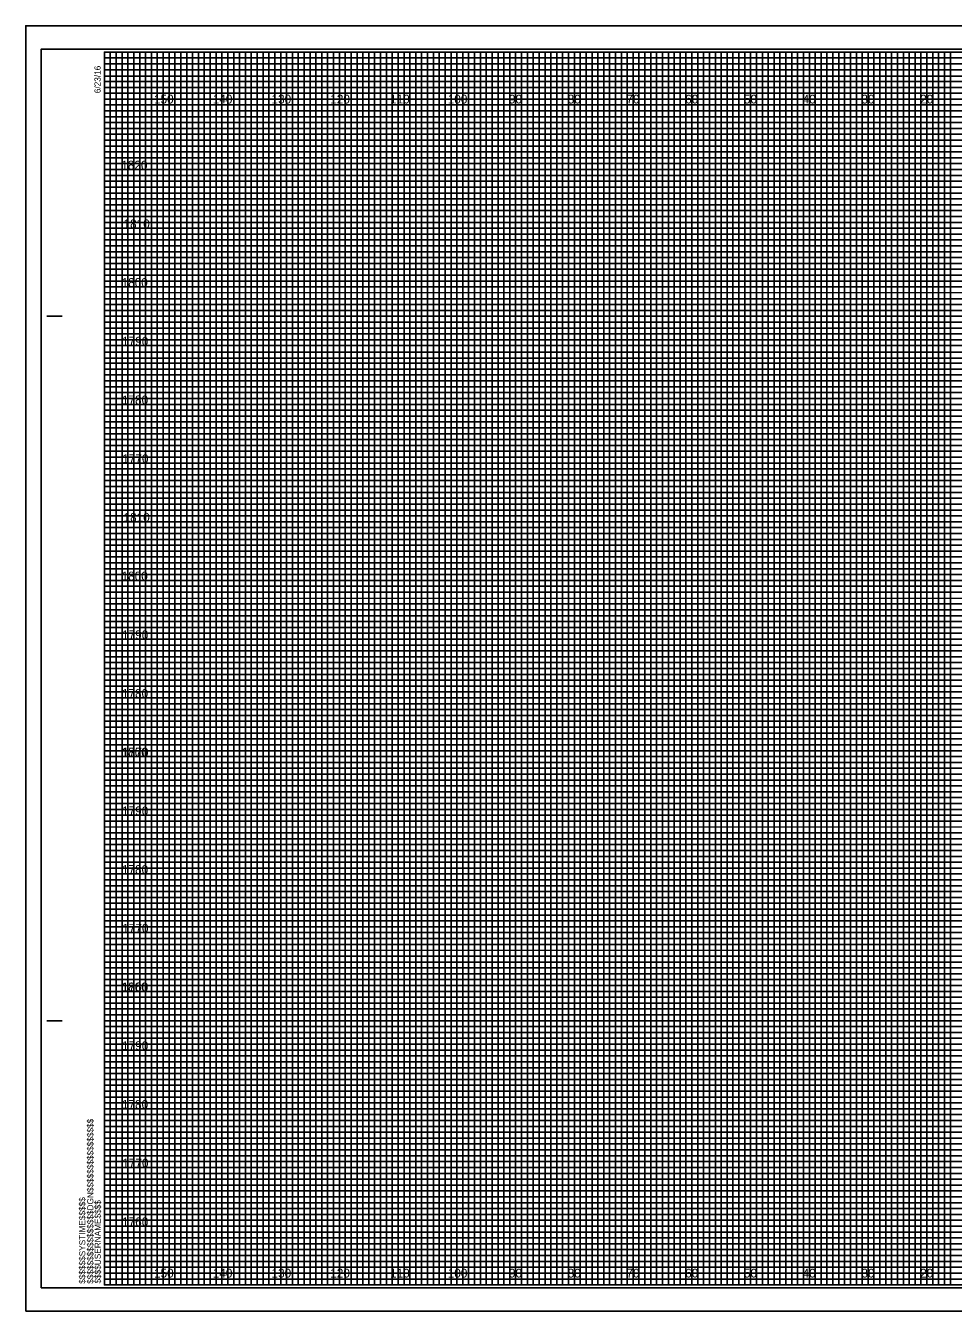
# Model space of a CAD drawing. Extents: x -13 to 323, y -5 to 874.
# Drawn here: x -13.4 to 144.5, y 215.5 to 434.5 of the extents above; entities that cross this region are included whole.
import ezdxf

# ---------------------------------------------------------------- set-up
doc = ezdxf.new("R2010")
doc.units = 0
for name, color, linetype in [('Prop XS Earthwork Shape', 7, 'Continuous'), ('Raster_Level_0', 7, 'Continuous'), ('Scratch_Level_3', 7, 'Continuous'), ('Sheet Cross Section CELL', 7, 'Continuous'), ('Sheet Cross Section Grid Middle CELL', 7, 'Continuous'), ('Sheet Cross Section Grid Minor 1 CELL', 7, 'Continuous'), ('Sheet Cross Section Grid Minor 2 CELL', 7, 'Continuous'), ('Sheet Cutting Line CELL', 7, 'Continuous'), ('Sheet DOT Grid CELL', 7, 'Continuous'), ('Sheet Plot Border Inside CELL', 7, 'Continuous'), ('Sheet Plot Border Outside CELL', 7, 'Continuous')]:
    doc.layers.add(name, color=color, linetype=linetype)

msp = doc.modelspace()

# ---------------------------------------------------------------- linework, layer by layer
at = {"layer": 'Prop XS Earthwork Shape'}
for p, q in [((10, 430), (0, 430)), ((10, 220), (10, 430)), ((30, 430), (20, 430)), ((20, 430), (20, 220)), ((30, 220), (30, 430)), ((50, 430), (40, 430)), ((40, 430), (40, 220)), ((50, 220), (50, 430)), ((70, 430), (60, 430)), ((60, 430), (60, 220)), ((70, 220), (70, 430)), ((90, 430), (80, 430)), ((80, 430), (80, 220)), ((90, 220), (90, 430)), ((110, 430), (100, 430)), ((100, 430), (100, 220)), ((110, 220), (110, 430)), ((130, 430), (120, 430)), ((120, 430), (120, 220)), ((130, 220), (130, 430)), ((150, 430), (140, 430)), ((140, 430), (140, 220)), ((20, 220), (10, 220)), ((40, 220), (30, 220)), ((60, 220), (50, 220)), ((80, 220), (70, 220)), ((100, 220), (90, 220)), ((120, 220), (110, 220)), ((140, 220), (130, 220))]:
    msp.add_line(p, q, dxfattribs=at)
for points in [[(0, 420), (320, 420), (320, 410), (0, 410)], [(0, 400), (320, 400), (320, 390), (0, 390)], [(0, 380), (320, 380), (320, 370), (0, 370)], [(0, 360), (320, 360), (320, 350), (0, 350)], [(0, 340), (320, 340), (320, 330), (0, 330)], [(0, 320), (320, 320), (320, 310), (0, 310)], [(0, 300), (320, 300), (320, 290), (0, 290)], [(0, 280), (320, 280), (320, 270), (0, 270)], [(0, 260), (320, 260), (320, 250), (0, 250)], [(0, 240), (320, 240), (320, 230), (0, 230)]]:
    msp.add_lwpolyline(points, dxfattribs=at)
at = {"layer": 'Sheet Cross Section CELL'}
for p, q in [((-9.8, 385), (-7.3, 385)), ((-9.7, 385), (-7.2, 385)), ((-9.8, 265), (-7.3, 265)), ((-9.7, 265), (-7.2, 265)), ((0, 220), (0, 220)), ((0, 220), (0, 220)), ((0, 220), (0, 220)), ((0, 220), (0, 220)), ((0, 220), (0, 220)), ((0, 220), (0, 220)), ((0, 220), (0, 220))]:
    msp.add_line(p, q, dxfattribs=at)
msp.add_lwpolyline([(320, 430), (0, 430), (0, 220), (320, 220)], close=True, dxfattribs=at)
at = {"layer": 'Sheet Cross Section Grid Middle CELL'}
for points in [[(0, 430), (5, 430), (5, 220), (15, 220), (15, 430), (25, 430), (25, 220), (35, 220), (35, 430), (45, 430), (45, 220), (55, 220), (55, 430), (65, 430), (65, 220), (75, 220), (75, 430), (85, 430), (85, 220), (95, 220), (95, 430), (105, 430), (105, 220), (115, 220), (115, 430), (125, 430), (125, 220), (135, 220), (135, 430), (145, 430)], [(0, 425), (275, 425)], [(0, 405), (320, 405), (320, 415), (0, 415)], [(0, 385), (320, 385), (320, 395), (0, 395)], [(0, 365), (320, 365), (320, 375), (0, 375)], [(0, 345), (320, 345), (320, 355), (0, 355)], [(0, 325), (320, 325), (320, 335), (0, 335)], [(0, 305), (320, 305), (320, 315), (0, 315)], [(0, 285), (320, 285), (320, 295), (0, 295)], [(0, 265), (320, 265), (320, 275), (0, 275)], [(0, 245), (320, 245), (320, 255), (0, 255)], [(0, 225), (320, 225), (320, 235), (0, 235)]]:
    msp.add_lwpolyline(points, dxfattribs=at)
at = {"layer": 'Sheet Cross Section Grid Minor 1 CELL'}
for p, q in [((0, 429), (260, 429)), ((260, 427.98), (0, 427.98)), ((0, 427.98), (0, 427)), ((0, 427), (260, 427)), ((260, 425.89), (0, 425.89)), ((0, 425.89), (0, 424)), ((0, 424), (320, 424))]:
    msp.add_line(p, q, dxfattribs=at)
for points in [[(0, 423), (270, 423), (320, 423), (320, 422), (0, 422)], [(0, 421), (320, 421), (320, 419), (0, 419)], [(0, 418), (320, 418), (320, 417), (0, 416.98)], [(0, 416), (320, 416), (320, 414), (0, 414)], [(0, 413), (320, 413), (320, 412), (0, 412)], [(0, 411), (320, 411), (320, 409), (0, 409)], [(0, 408), (320, 408), (320, 407), (0, 407)], [(0, 406), (320, 406), (320, 404), (0, 404)], [(0, 403), (320, 403), (320, 402), (0, 402)], [(0, 401), (320, 401), (320, 399), (0, 399)], [(0, 398), (320, 398), (320, 397), (0, 397)], [(0, 396), (320, 396), (320, 393.95), (320, 393), (320, 392), (0, 392)], [(0, 394), (320, 394), (320, 393), (0, 393)], [(0, 391), (320, 391), (320, 389), (0, 389.03)], [(0, 389.03), (320, 389), (320, 388), (0, 388)], [(0, 387), (320, 387), (320, 386), (0, 386)], [(0, 384), (320, 384), (320, 383), (0, 383)], [(0, 382), (320, 382), (320, 381), (0, 381)], [(-0.07, 378.89), (320, 378.89), (320, 377.88), (-0.07, 377.88)], [(0, 377), (320, 377), (320, 376), (0, 376)], [(0, 374), (320, 374), (320, 373), (0, 373)], [(0, 372), (320, 372), (320, 371), (0, 371)], [(0, 369), (320, 369), (320, 368), (0, 368)], [(0, 367), (320, 367), (320, 366), (0, 366)], [(0, 364), (320, 364), (320, 363), (0, 363)], [(0, 362), (320, 362), (320, 361), (0, 361)], [(0, 359), (320, 359), (319.99, 357.98), (0, 358)], [(0, 357), (320, 357), (320, 356), (0, 356)], [(0, 354), (320, 354), (320, 353), (0, 353)], [(0, 352), (320, 352), (320, 351), (0, 351)], [(0, 349), (320, 349), (320, 348), (0, 348)], [(0, 347), (320, 347), (320, 346), (0, 346)], [(0, 344), (320, 344), (320, 343), (0, 343)], [(0, 342), (320, 342), (320, 341), (0, 341)], [(0, 339), (320, 339), (320, 338), (0, 338)], [(0, 336.99), (320.07, 336.91), (320, 336), (0, 336)], [(0, 334), (320, 334), (320, 333), (0, 333)], [(0, 332), (320, 332), (320, 331), (0, 331)], [(0, 329), (320, 329), (320, 328), (0, 328)], [(0, 327), (320, 327), (320, 326), (0, 326)], [(0, 324), (320, 324), (320, 323), (0, 323)], [(0, 322), (320, 322), (320, 321), (0, 321)], [(0, 319), (320, 319), (320, 318), (0, 318)], [(0, 317), (320, 317), (320, 316), (0, 316)], [(0, 314), (320, 314), (320, 313), (0, 313)], [(0, 312), (320, 312), (320, 311), (0, 311)], [(0, 309), (320, 309), (320, 308), (0, 308)], [(0, 307), (320, 307), (320, 306), (0, 306)], [(0, 304), (320, 304), (320, 303), (0, 303)], [(0, 302), (320, 302), (320, 301), (0, 301)], [(0, 299), (320, 299), (319.99, 297.98), (0, 298)], [(0, 297), (320, 297), (320, 296), (0, 296)], [(0, 294), (320, 294), (320, 293), (0, 293)], [(0, 292), (320, 292), (320, 291), (0, 291)], [(0, 289), (320, 289), (320, 288), (0, 288)], [(0, 287), (320, 287), (320, 286), (0, 286)], [(0, 284), (320, 284), (320, 283), (0, 283)], [(0, 282), (320, 282), (320, 281), (0, 281)], [(0, 279), (320, 279), (320, 278), (0, 278)], [(0, 276.99), (320.07, 276.91), (320, 276), (0, 276)], [(0, 274), (320, 274), (320, 273), (0, 273)], [(0, 272), (320, 272), (320, 271), (0, 271)], [(0, 269), (320, 269), (320, 268), (0, 268)], [(0, 267), (320, 267), (320, 266), (0, 266)], [(0, 264), (320, 264), (320, 263), (0, 263)], [(0, 262), (320, 262), (320, 261), (0, 261)], [(0, 259), (320, 259), (320, 258), (0, 258)], [(0, 257), (320, 257), (320, 256), (0, 256)], [(0, 254), (320, 254), (320, 253), (0, 253)], [(0, 252), (320, 252), (320, 251), (0, 251)], [(0, 249), (320, 249), (320, 248), (0, 248)], [(0, 247), (320, 247), (320, 246), (0, 246)], [(0, 244), (320, 244), (320, 243), (0, 243)], [(0, 242), (320, 242), (320, 241), (0, 241)], [(0, 239), (320, 239), (320, 238), (0, 238)], [(0, 237), (320, 237), (320, 236), (0, 236)], [(0, 234), (320, 234), (320, 233), (0, 233)], [(0, 232), (320, 232), (320, 231), (0, 231)], [(0, 229), (320, 229), (320, 228), (0, 228)], [(0, 227), (320, 227), (320, 226), (0, 226)], [(0, 224), (320, 224), (320, 223), (0, 223)], [(0, 222), (320, 222), (320, 221), (0, 221)]]:
    msp.add_lwpolyline(points, dxfattribs=at)
at = {"layer": 'Sheet Cross Section Grid Minor 2 CELL'}
for points in [[(0, 220), (1, 220), (1, 430), (2, 430), (2, 220)], [(2, 220), (3, 220), (3, 430), (4, 430), (4, 220)], [(5, 220), (6, 220), (6, 430), (7, 430), (7, 220)], [(7, 220), (8, 220), (8, 430), (9, 430), (9, 220)], [(10, 220), (11, 220), (11, 430), (12, 430), (12, 220)], [(12, 220), (13, 220), (13, 430), (14, 430), (14, 220)], [(15, 220), (16, 220), (16, 430), (17, 430), (17, 220)], [(17, 220), (18, 220), (18, 430), (19, 430), (19, 220)], [(20, 220), (21, 220), (21, 430), (22, 430), (22, 220)], [(22, 220), (23, 220), (23, 430), (24, 430), (24, 220)], [(25, 220), (26, 220), (26, 430), (27, 430), (27, 220)], [(27, 220), (28, 220), (28, 430), (29, 430), (29, 220)], [(30, 220), (31, 220), (31, 430), (32, 430), (32, 220)], [(32, 220), (33, 220), (33, 430), (34, 430), (34, 220)], [(35, 220), (36, 220), (36, 430), (37, 430), (37, 220)], [(37, 220), (38, 220), (38, 430), (39, 430), (39, 220)], [(40, 220), (41, 220), (41, 430), (42, 430), (42, 220)], [(42, 220), (43, 220), (43, 430), (44, 430), (44, 220)], [(45, 220), (46, 220), (46, 430), (47, 430), (47, 220)], [(47, 220), (48, 220), (48, 430), (49, 430), (49, 220)], [(50, 220), (51, 220), (51, 430), (52, 430), (52, 220)], [(52, 220), (53, 220), (53, 430), (54, 430), (54, 220)], [(55, 220), (56, 220), (56, 430), (57, 430), (57, 220)], [(57, 220), (58, 220), (58, 430), (59, 430), (59, 220)], [(60, 220), (61, 220), (61, 430), (62, 430), (62, 220)], [(62, 220), (63, 220), (63, 430), (64, 430), (64, 220)], [(65, 220), (66, 220), (66, 430), (67, 430), (67, 220)], [(67, 220), (68, 220), (68, 430), (69, 430), (69, 220)], [(70, 220), (71, 220), (71, 430), (72, 430), (72, 220)], [(72, 220), (73, 220), (73, 430), (74, 430), (74, 220)], [(75, 220), (76, 220), (76, 430), (77, 430), (77, 220)], [(77, 220), (78, 220), (78, 430), (79, 430), (79, 220)], [(80, 220), (81, 220), (81, 430), (82, 430), (82, 220)], [(82, 220), (83, 220), (83, 430), (84, 430), (84, 220)], [(85, 220), (86, 220), (86, 430), (87, 430), (87, 220)], [(87, 220), (88, 220), (88, 430), (89, 430), (89, 220)], [(90, 220), (91, 220), (91, 430), (92, 430), (92, 220)], [(92, 220), (93, 220), (93, 430), (94, 430), (94, 220)], [(95, 220), (96, 220), (96, 430), (97, 430), (97, 220)], [(97, 220), (98, 220), (98, 430), (99, 430), (99, 220)], [(100, 220), (101, 220), (101, 430), (102, 430), (102, 220)], [(102, 220), (103, 220), (103, 430), (104, 430), (104, 220)], [(105, 220), (106, 220), (106, 430), (107, 430), (107, 220)], [(107, 220), (108, 220), (108, 430), (109, 430), (109, 220)], [(110, 220), (111, 220), (111, 430), (112, 430), (112, 220)], [(112, 220), (113, 220), (113, 430), (114, 430), (114, 220)], [(115, 220), (116, 220), (116, 430), (117, 430), (117, 220)], [(117, 220), (118, 220), (118, 430), (119, 430), (119, 220)], [(120, 220), (121, 220), (121, 430), (122, 430), (122, 220)], [(122, 220), (123, 220), (123, 430), (124, 430), (124, 220)], [(125, 220), (126, 220), (126, 430), (127, 430), (127, 220)], [(127, 220), (128, 220), (128, 430), (129, 430), (129, 220)], [(130, 220), (131, 220), (131, 430), (132, 430), (132, 220)], [(132, 220), (133, 220), (133, 430), (134, 430), (134, 220)], [(135, 220), (136, 220), (136, 430), (137, 430), (137, 220)], [(137, 220), (138, 220), (138, 430), (139, 430), (139, 220)], [(140, 220), (141, 220), (141, 430), (142, 430), (142, 220)], [(142, 220), (143, 220), (143, 430), (144, 430), (144, 220)]]:
    msp.add_lwpolyline(points, dxfattribs=at)
at = {"layer": 'Sheet Cutting Line CELL'}
for p, q in [((323.3, 434.5), (-13.4, 434.5)), ((-13.4, 434.5), (-13.4, 215.5)), ((-13.4, 215.5), (323.3, 215.5))]:
    msp.add_line(p, q, dxfattribs=at)
at = {"layer": 'Sheet DOT Grid CELL'}
for p, q in [((10, 220), (10, 430)), ((20, 220), (20, 430)), ((30, 220), (30, 430)), ((40, 220), (40, 430)), ((50, 220), (50, 430)), ((60, 220), (60, 430)), ((70, 220), (70, 430)), ((80, 220), (80, 430)), ((90, 220), (90, 430)), ((100, 220), (100, 430)), ((110, 220), (110, 430)), ((120, 220), (120, 430)), ((130, 220), (130, 430)), ((140, 220), (140, 430)), ((0, 420), (320, 420)), ((0, 410), (320, 410)), ((0, 400), (320, 400)), ((0, 390), (320, 390)), ((0, 380), (320, 380)), ((0, 370), (320, 370)), ((0, 360), (320, 360)), ((0, 350), (320, 350)), ((0, 340), (320, 340)), ((0, 330), (320, 330)), ((0, 320), (320, 320)), ((0, 310), (320, 310)), ((0, 300), (320, 300)), ((0, 290), (320, 290)), ((0, 280), (320, 280)), ((0, 270), (320, 270)), ((0, 260), (320, 260)), ((0, 250), (320, 250)), ((0, 240), (320, 240)), ((0, 230), (320, 230))]:
    msp.add_line(p, q, dxfattribs=at)
at = {"layer": 'Sheet Plot Border Inside CELL'}
msp.add_lwpolyline([(-10.8, 219.5), (322.4, 219.5), (322.4, 430.5), (-10.8, 430.5)], close=True, dxfattribs=at)
at = {"layer": 'Sheet Plot Border Outside CELL'}
msp.add_lwpolyline([(-13.4, 215.5), (323.3, 215.5), (323.3, 434.5), (-13.4, 434.5)], close=True, dxfattribs=at)

# ---------------------------------------------------------------- texts
at = {"layer": 'Raster_Level_0'}
for s, p in [('150', (8.44, 421.25)), ('140', (18.44, 421.25)), ('130', (28.44, 421.25)), ('120', (38.44, 421.25)), ('110', (48.62, 421.25)), ('100', (58.44, 421.25)), ('90', (68.86, 421.25)), ('80', (78.86, 421.25)), ('70', (88.86, 421.25)), ('60', (98.86, 421.25)), ('50', (108.86, 421.25)), ('40', (118.86, 421.25)), ('30', (128.86, 421.25)), ('20', (138.86, 421.25)), ('150', (8.44, 221.25)), ('140', (18.44, 221.25)), ('130', (28.44, 221.25)), ('120', (38.44, 221.25)), ('110', (48.62, 221.25)), ('100', (58.44, 221.25)), ('90', (68.86, 221.25)), ('80', (78.86, 221.25)), ('70', (88.86, 221.25)), ('60', (98.86, 221.25)), ('50', (108.86, 221.25)), ('40', (118.86, 221.25)), ('30', (128.86, 221.25)), ('20', (138.86, 221.25))]:
    msp.add_text(s, height=1.5, dxfattribs=at).set_placement(p)
at = {"layer": 'Scratch_Level_3'}
for s, p in [('1820', (2.87, 410)), ('1810', (3.25, 400)), ('1800', (2.92, 390)), ('1790', (3, 380)), ('1780', (2.98, 370)), ('1770', (3.04, 360)), ('1810', (3.25, 350)), ('1800', (2.92, 340)), ('1790', (3, 330)), ('1780', (2.98, 320)), ('1800', (2.92, 310)), ('1770', (3.04, 310)), ('1790', (3, 300)), ('1780', (2.98, 290)), ('1770', (3.04, 280)), ('1800', (2.92, 270)), ('1760', (3, 270)), ('1790', (3, 260)), ('1780', (2.98, 250)), ('1770', (3.04, 240)), ('1760', (3, 230))]:
    msp.add_text(s, height=1.5, dxfattribs=at).set_placement(p)
at = {"layer": 'Sheet Cross Section CELL'}
for s, p in [('6/23/16', (-0.65, 423)), ('$$$$$$$$$$$$$$$$DGN$$$$$$$$$$$$$$$$', (-1.88, 220.18)), ('$$$$$$SYSTIME$$$$$', (-3.26, 220.18)), ('$$$$USERNAME$$$$', (-0.62, 220.23))]:
    msp.add_text(s, height=1.05, rotation=90, dxfattribs=at).set_placement(p)

doc.saveas('drawing.dxf')
